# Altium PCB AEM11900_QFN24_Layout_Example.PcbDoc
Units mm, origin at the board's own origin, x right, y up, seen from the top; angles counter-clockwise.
Board outline 76 x 49 mm, 4 copper layers (Component Side, Ground Plane, Power Plane, Solder Side), stack 1.563 mm thick; 9 components, 21 nets, 41 pads, 18 vias.
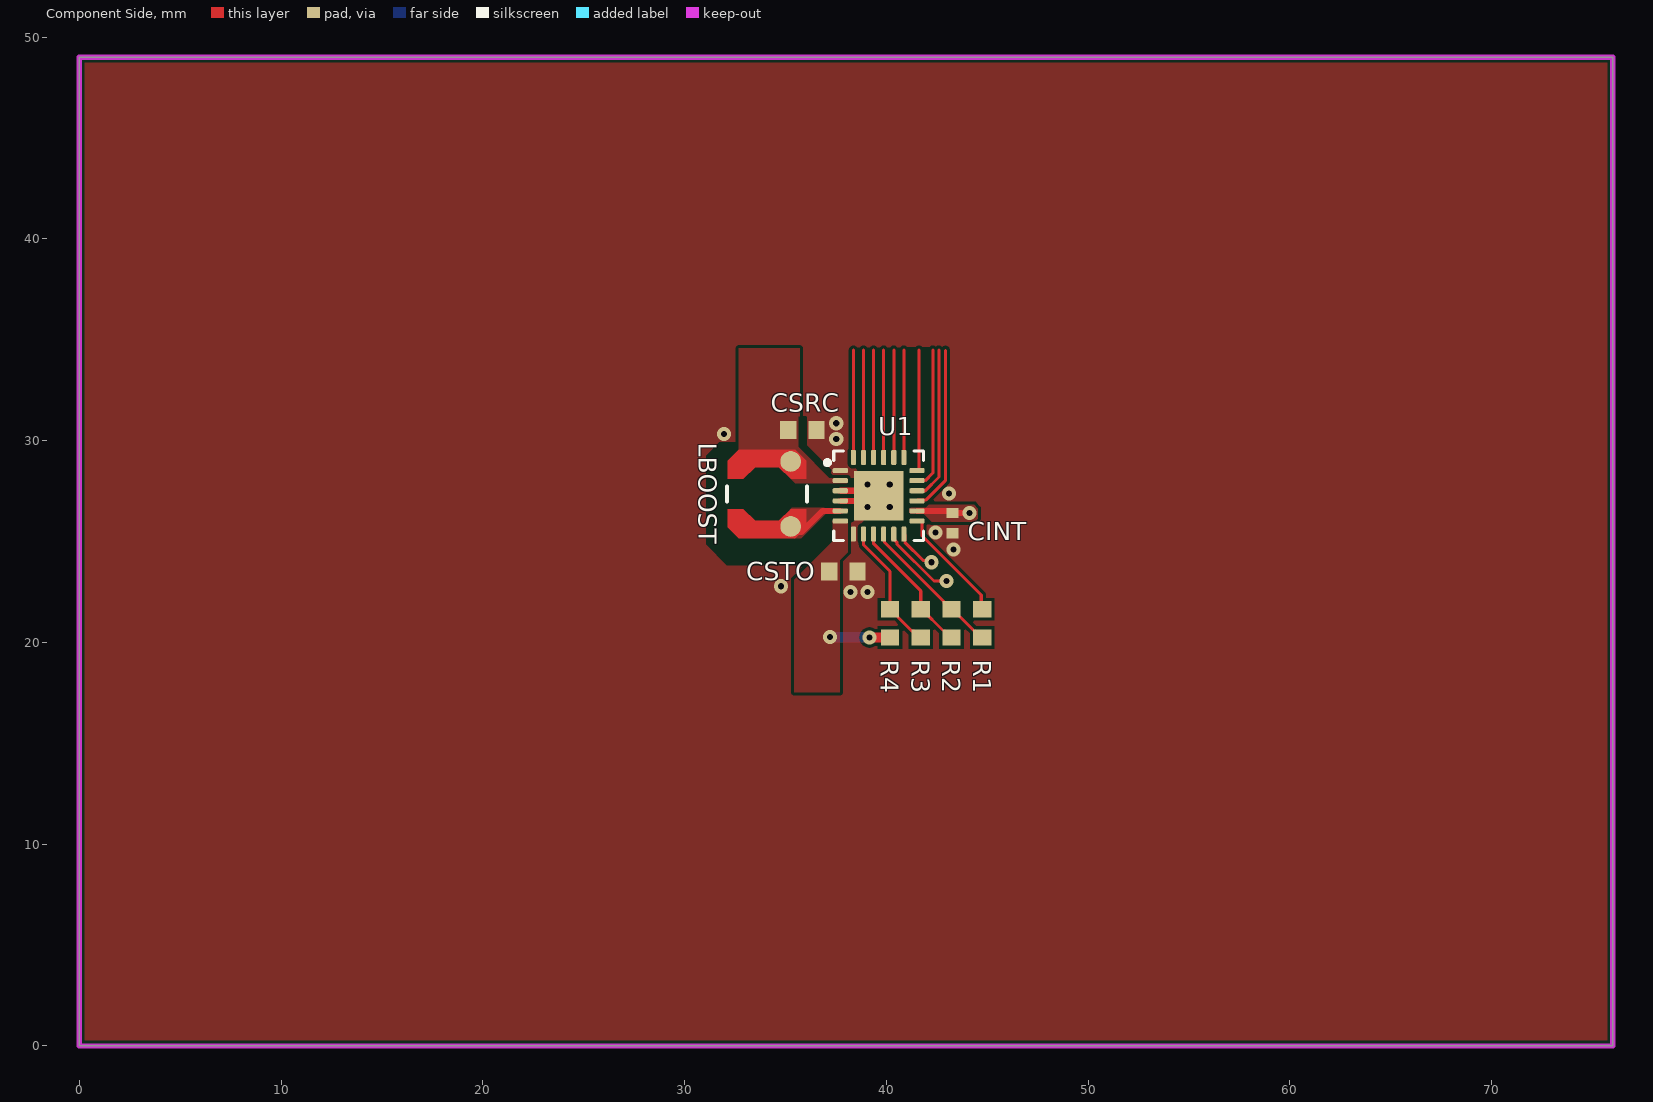
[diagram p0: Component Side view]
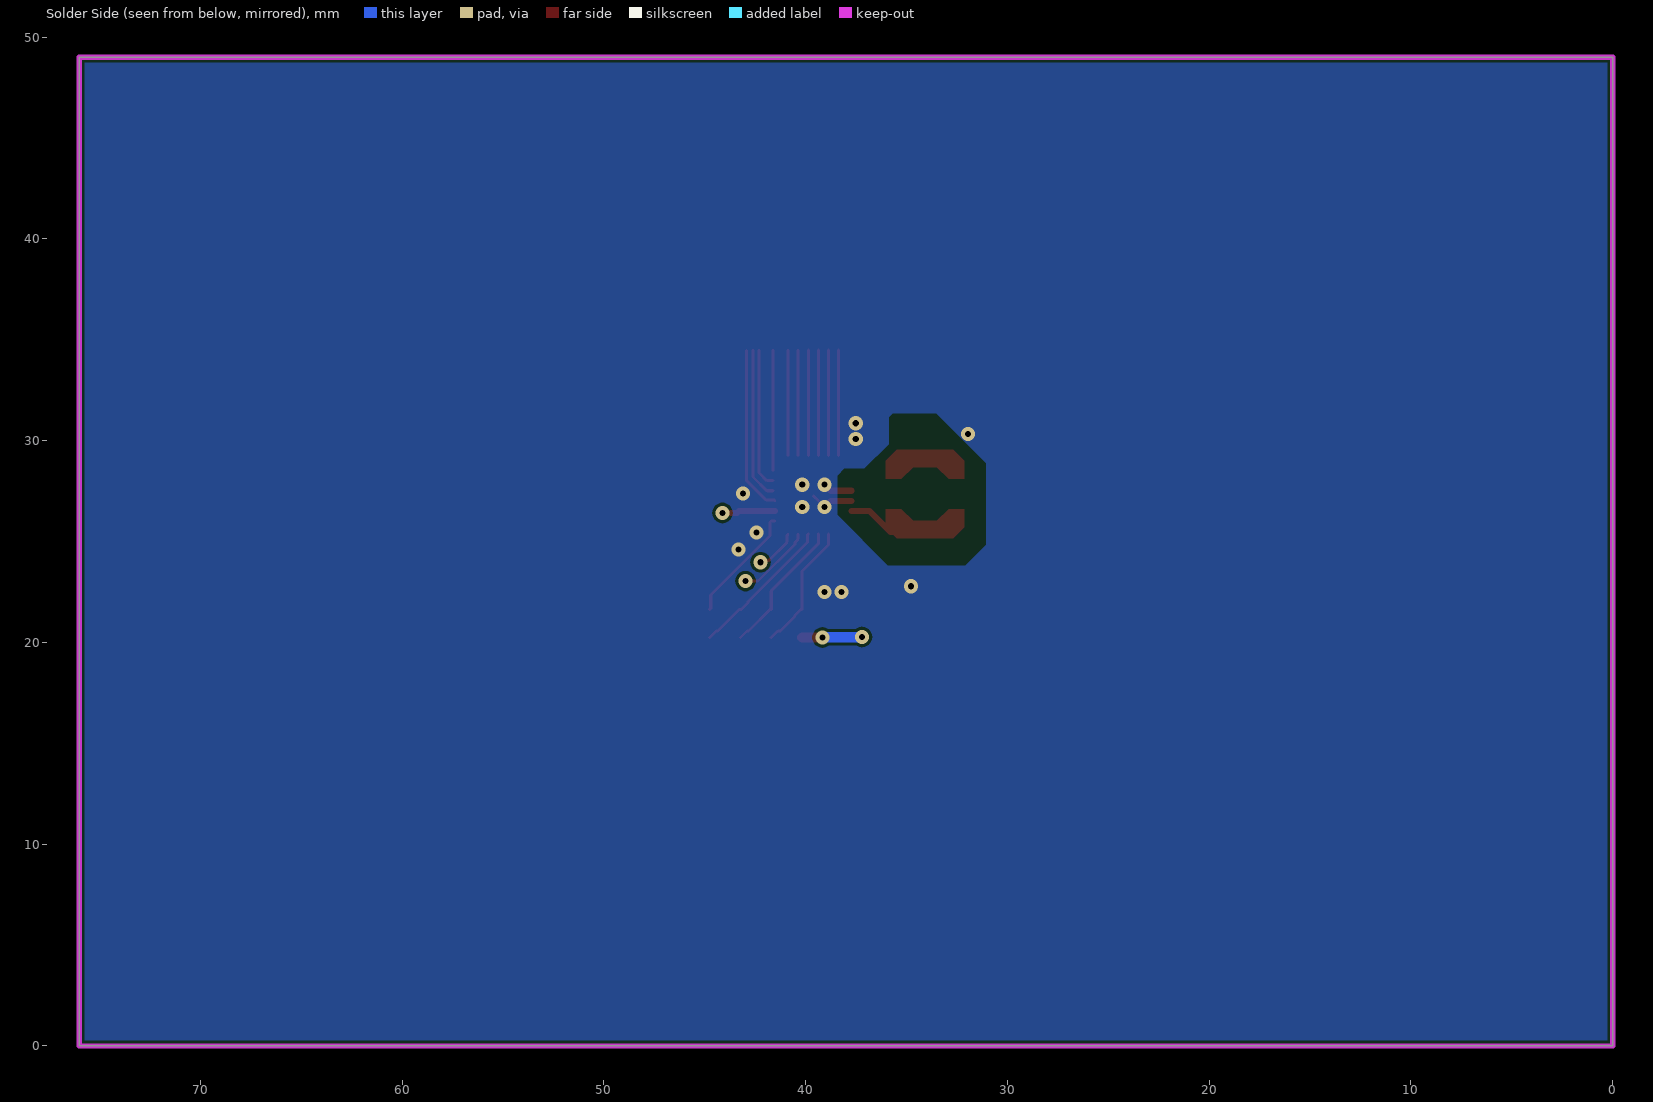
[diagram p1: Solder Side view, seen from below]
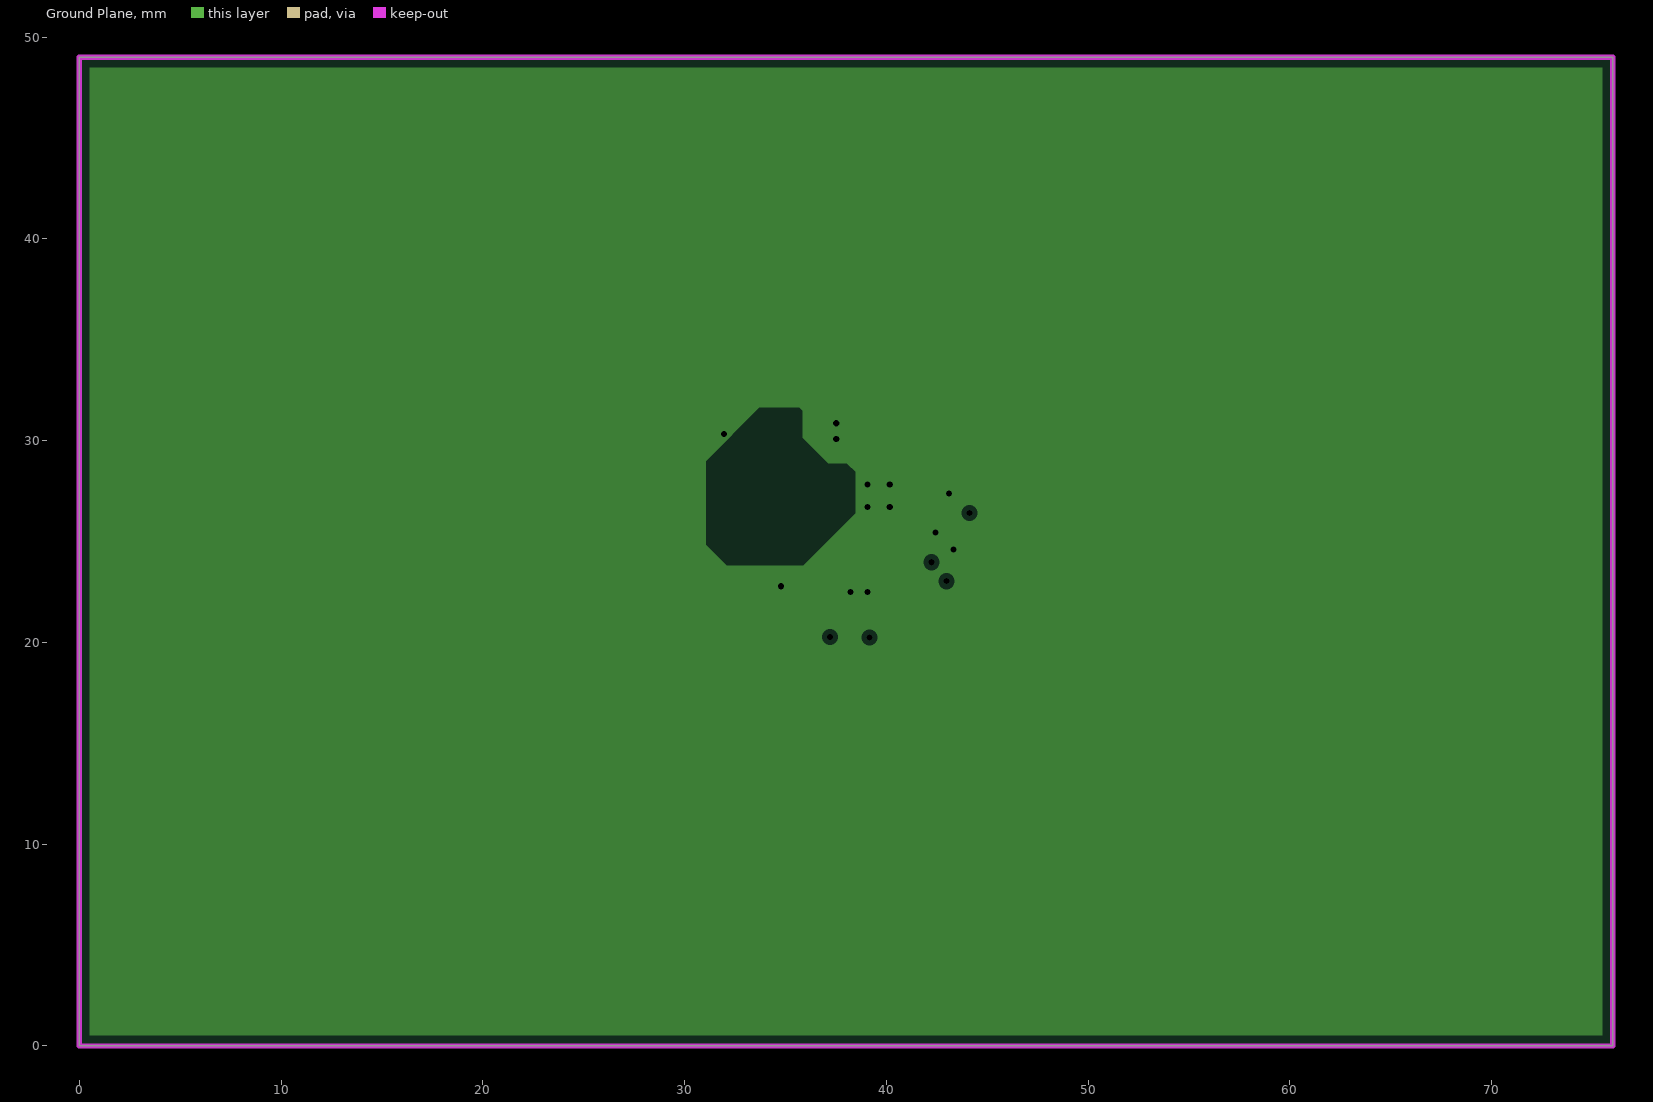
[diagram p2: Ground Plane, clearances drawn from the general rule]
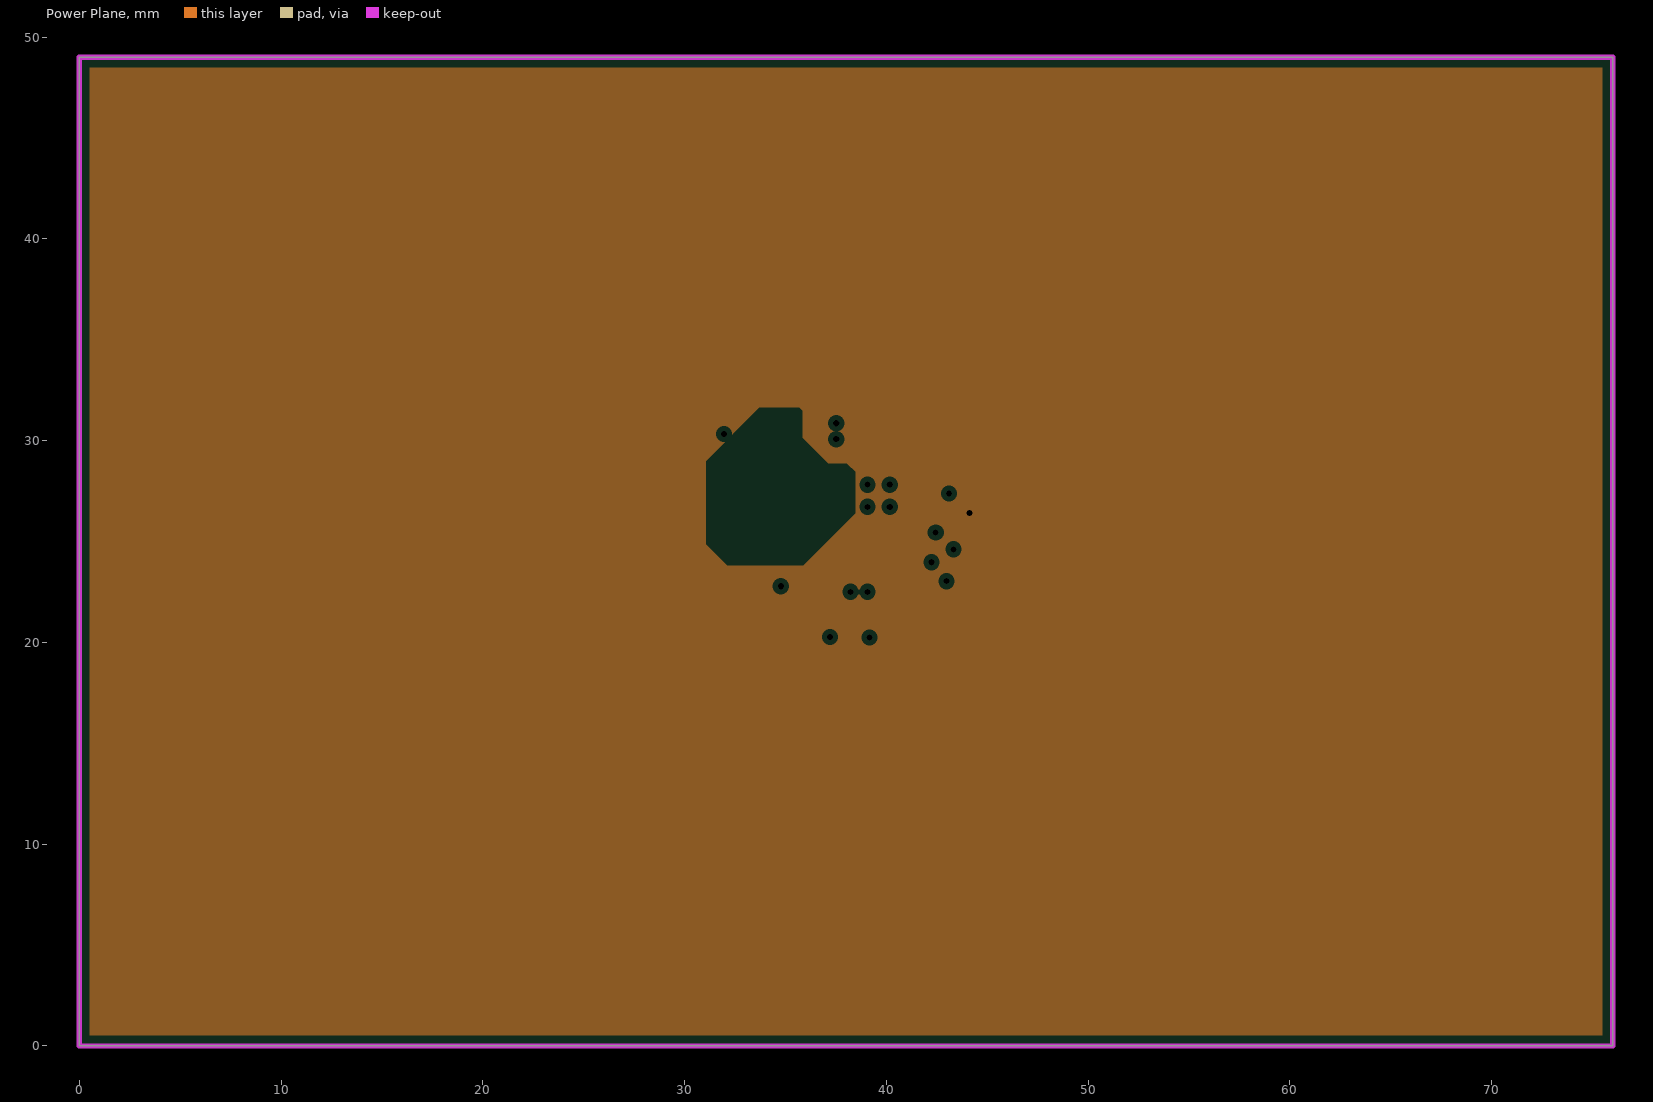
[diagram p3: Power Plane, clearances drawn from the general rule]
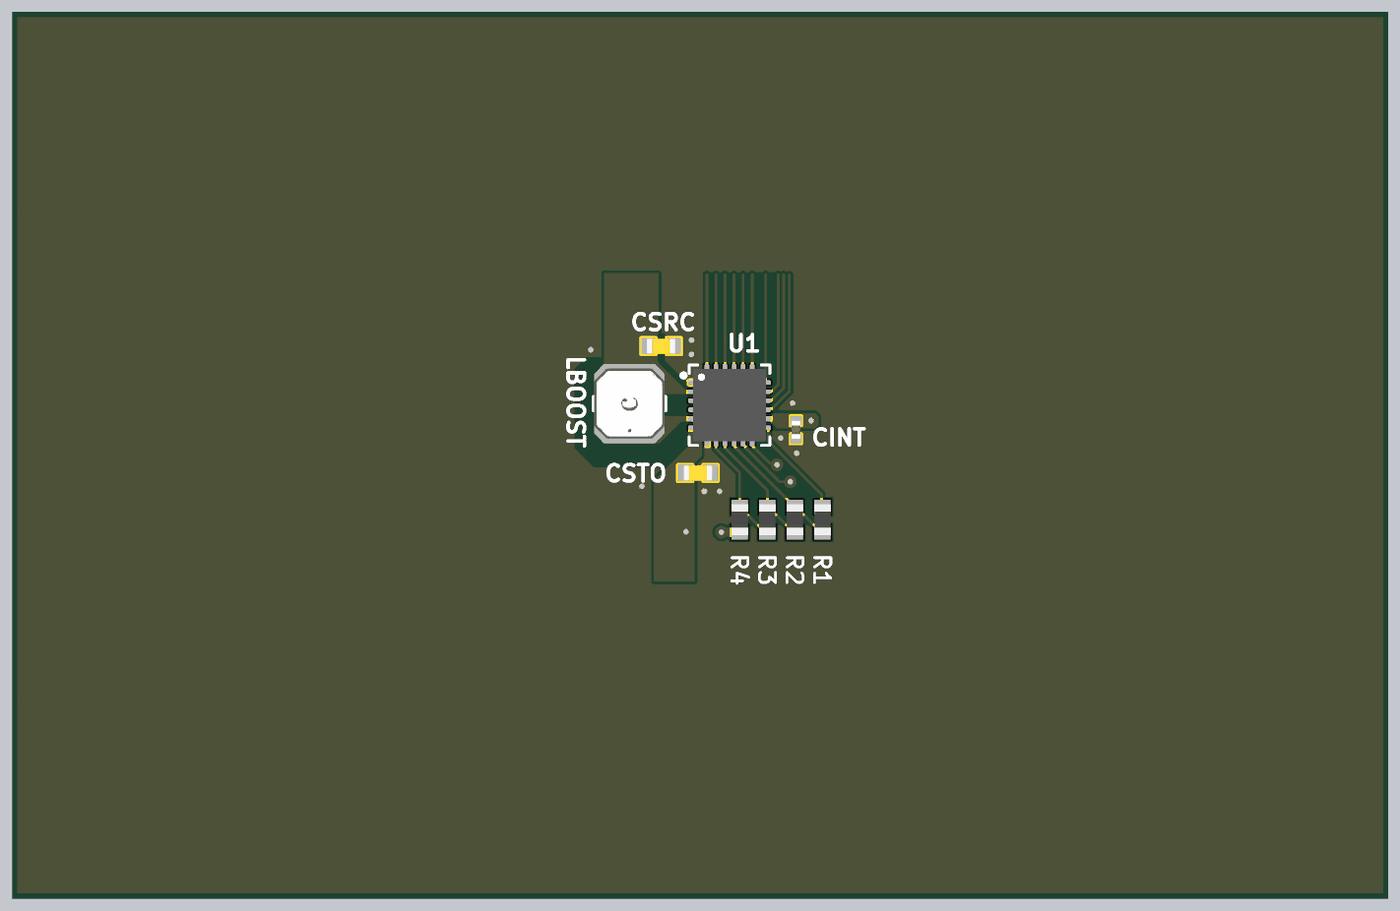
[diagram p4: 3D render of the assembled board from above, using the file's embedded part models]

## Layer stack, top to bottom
Top Solder: solder mask 0.0102, Solder Resist, Dk 3.5
Component Side: signal copper 0.0356
Dielectric 1: prepreg 0.36, Prepreg 7628, Dk 4.2
Ground Plane: plane copper 0.036, net GND
Dielectric 3: core 0.7, Core, Dk 4.2
Power Plane: plane copper 0.036, net VINT
Dielectric 4: prepreg 0.36, Prepreg 7628, Dk 4.2
Solder Side: signal copper 0.0356
Bottom Solder: solder mask 0.0102, Solder Resist, Dk 3.5

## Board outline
0,0 0,49 76,49 76,0

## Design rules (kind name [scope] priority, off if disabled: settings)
Clearance Clearance_SW [InNet('SWBOOST') or InNet('SWBUCK') vs InNet('GND')] p1: gap=0.15 ignorepadtopadclearanceinfootprint=FALSE except(0.5: Arc-Poly Track-Poly SMDPad-Poly THPad-Poly Via-Poly Fill-Poly Poly-Poly Poly-Region)
Clearance [All] p2: gap=0.15 ignorepadtopadclearanceinfootprint=FALSE
ComponentClearance ComponentClearance_DIL [HasFootprint('DIL_PAD') vs HasFootprint('DIL_PAD')] p1: gap=0 collisioncheckmode=3 verticalgap=0 showdistances=FALSE
ComponentClearance [All] p2: gap=0.254 collisioncheckmode=3 verticalgap=0.254 showdistances=FALSE
DiffPairsRouting [All] p1: maxlimit=0.254 minlimit=0.254 mostfreqgap=0.254 toplayer_minwidth=0.381 toplayer_maxwidth=0.381 toplayer_prefwidth=0.381 bottomlayer_minwidth=0.381 bottomlayer_maxwidth=0.381 bottomlayer_prefwidth=0.381 substack1={24748C9E-C2FE-4590-BE0C-AD6E21E98903} toplayer_{24748c9e-c2fe-4590-be0c-ad6e21e98903}_minwidth=0.381 toplayer_{24748c9e-c2fe-4590-be0c-ad6e21e98903}_maxwidth=0.381 toplayer_{24748c9e-c2fe-4590-be0c-ad6e21e98903}_prefwidth=0.381 bottomlayer_{24748c9e-c2fe-4590-be0c-ad6e21e98903}_minwidth=0.381 bottomlayer_{24748c9e-c2fe-4590-be0c-ad6e21e98903}_maxwidth=0.381 bottomlayer_{24748c9e-c2fe-4590-be0c-ad6e21e98903}_prefwidth=0.381 substack2={CAEF0C9C-1F67-4FFA-A1CA-0FD6FF6C2F90} toplayer_{caef0c9c-1f67-4ffa-a1ca-0fd6ff6c2f90}_minwidth=0.381 toplayer_{caef0c9c-1f67-4ffa-a1ca-0fd6ff6c2f90}_maxwidth=0.381 toplayer_{caef0c9c-1f67-4ffa-a1ca-0fd6ff6c2f90}_prefwidth=0.381 bottomlayer_{caef0c9c-1f67-4ffa-a1ca-0fd6ff6c2f90}_minwidth=0.381 bottomlayer_{caef0c9c-1f67-4ffa-a1ca-0fd6ff6c2f90}_maxwidth=0.381 bottomlayer_{caef0c9c-1f67-4ffa-a1ca-0fd6ff6c2f90}_prefwidth=0.381 substack3={D99B185B-21CD-406C-9F05-D1849F64E374} toplayer_{d99b185b-21cd-406c-9f05-d1849f64e374}_minwidth=0.381 toplayer_{d99b185b-21cd-406c-9f05-d1849f64e374}_maxwidth=0.381 toplayer_{d99b185b-21cd-406c-9f05-d1849f64e374}_prefwidth=0.381 bottomlayer_{d99b185b-21cd-406c-9f05-d1849f64e374}_minwidth=0.381 bottomlayer_{d99b185b-21cd-406c-9f05-d1849f64e374}_maxwidth=0.381 bottomlayer_{d99b185b-21cd-406c-9f05-d1849f64e374}_prefwidth=0.381 maxuncoupledlength=12.7
HoleToHoleClearance [All] p1: gap=0.2 allowstackedmicrovias=TRUE
MinimumAnnularRing [All] p1: minimumring=0.15
MinimumSolderMaskSliver [All] p1: minsoldermaskwidth=0
PlaneClearance [All] p1: clearance=0.254
PlaneConnect "Plane Force direct connect" [InComponent('M1') or InComponent('M2') or InComponent('M3') or InComponent('M4') or InComponent('TP1') or InComponent('TP2') or InComponent('TP3')] p1: planeconnectstyle=Direct reliefexpansion=0.508 reliefentries=4 reliefconductorwidth=0.5 reliefairgap=0.254
PlaneConnect [All] p2: pad.planeconnectstyle=Relief pad.reliefexpansion=0.2 pad.reliefentries=4 pad.reliefconductorwidth=0.5 pad.reliefairgap=0.15 via.planeconnectstyle=Direct via.reliefexpansion=0.2 via.reliefentries=4 via.reliefconductorwidth=0.254 via.reliefairgap=0.15
PolygonConnect "Poly Force direct connect" [InComponent('M1') or InComponent('M2') or InComponent('M3') or InComponent('M4')] p1: connectstyle=Direct reliefconductorwidth=0.254 reliefentries=4 polygonreliefangle="90 Angle" airgapwidth=0.254
PolygonConnect [All] p2: thpad.connectstyle=Relief thpad.reliefconductorwidth=0.35 thpad.reliefentries=4 thpad.polygonreliefangle="90 Angle" thpad.airgapwidth=0.15 smdpad.connectstyle=Direct smdpad.reliefconductorwidth=0.5 smdpad.reliefentries=4 smdpad.polygonreliefangle="90 Angle" smdpad.airgapwidth=0.15 via.connectstyle=Direct via.reliefconductorwidth=0.35 via.reliefentries=4 via.polygonreliefangle="90 Angle" via.airgapwidth=0.15
RoutingVias [All] p1: holewidth=0.3 width=0.7 viastyle="Through Hole" minholewidth=0.3 minwidth=0.7 maxholewidth=0.3 maxwidth=0.7
SilkToSilkClearance [All] p1: silktosilkclearance=0
SilkToSolderMaskClearance [IsPad] p1: minsilkscreentomaskgap=0.1 clearancetoexposedcopper=TRUE
SolderMaskExpansion "tented vias" [IsVia] p1: expansion=0.15 istentingtop=TRUE
SolderMaskExpansion [All] p2: expansion=0.11 istentingtop=FALSE
SupplyNets "Schematic Supply Nets_2" [InNet('STO')] p1: voltage=0.000
SupplyNets "Schematic Supply Nets_1" [InNet('GND')] p2: voltage=0.000
SupplyNets "Schematic Supply Nets" [InNet('VINT')] p3: voltage=0.000
Width [All] p1: maxlimit=2 minlimit=0.15 preferedwidth=0.2 substack1={24748C9E-C2FE-4590-BE0C-AD6E21E98903} substack2={CAEF0C9C-1F67-4FFA-A1CA-0FD6FF6C2F90} substack3={D99B185B-21CD-406C-9F05-D1849F64E374} minimp=50.000000 maximp=50.000000 favimp=50.000000
22 further rules are at their usual default settings.

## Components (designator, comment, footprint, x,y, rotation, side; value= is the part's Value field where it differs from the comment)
CINT "10uF" C0402_[1005] 43.282,25.908 r90 top
CSRC "10uF" C0603_[1608] 35.839,30.531 r180 top
CSTO "47uF" C0603_[1608] 37.871,23.52 r180 top
LBOOST "33uH" Coilcraft-LPS4018 34.087,27.356 r90 top
R1 "TBD" Resistor_0603_[1608] 44.753,20.941 r270 top
R2 "TBD" Resistor_0603_[1608] 43.229,20.941 r270 top
R3 "TBD" Resistor_0603_[1608] 41.705,20.941 r270 top
R4 "TBD" Resistor_0603_[1608] 40.181,20.941 r270 top
U1 "AEM11900_QFN24" QFN24_4x4mm_PITCH_0.5mm_PAD_2.45mm 39.617,27.266 r0 top

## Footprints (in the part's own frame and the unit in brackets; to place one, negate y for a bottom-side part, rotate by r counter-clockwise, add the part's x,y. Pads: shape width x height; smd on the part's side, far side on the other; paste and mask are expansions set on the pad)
C0402_[1005] [mm] "Chip Capacitor, Body 1.0x0.5mm, IPC High Density"
  rect 0.5x0.6 smd: 1(-0.5,0) 2(0.5,0)
  body extent -0.5,-0.25 0.5,0.25, height 0.7
C0603_[1608] [mm]
  rect 0.8x0.9 smd: 1(-0.7,0) 2(0.7,0)
  body extent -0.8,-0.43 0.8,0.43, height 0.8
Coilcraft-LPS4018 [mm]
  round 1.026 smd paste+0 mask+0: 1(-1.611,-1.175) 2(1.611,-1.175)
  Component Side region: 0.75,1.945 1.64,1.945 2.2,1.395 2.2,-1.395 1.64,-1.945 0.75,-1.945 0.75,-1.17 1.33,-0.575 1.33,0.575 0.75,1.17
  Component Side region: -0.75,1.945 -1.64,1.945 -2.2,1.395 -2.2,-1.395 -1.64,-1.945 -0.75,-1.945 -0.75,-1.17 -1.33,-0.575 -1.33,0.575 -0.75,1.17
  silkscreen extent -0.37,-1.99 0.37,1.99, body extent -2.3,-2.09 2.3,2.09, height 0.25
QFN24_4x4mm_PITCH_0.5mm_PAD_2.45mm [mm] "QFN, 24-Leads, Body 4.00x4.00mm, Pitch 0.50mm, Thermal Pad 2.45x2.45mm"
  rrect50% 0.75x0.25 smd: 1(-1.9,1.25) 2(-1.9,0.75) 3(-1.9,0.25) 4(-1.9,-0.25) 5(-1.9,-0.75) 6(-1.9,-1.25) 13(1.9,-1.25) 14(1.9,-0.75) 15(1.9,-0.25) 16(1.9,0.25) 17(1.9,0.75) 18(1.9,1.25)
  rrect50% 0.25x0.75 smd: 7(-1.25,-1.9) 8(-0.75,-1.9) 9(-0.25,-1.9) 10(0.25,-1.9) 11(0.75,-1.9) 12(1.25,-1.9) 19(1.25,1.9) 20(0.75,1.9) 21(0.25,1.9) 22(-0.25,1.9) 23(-0.75,1.9) 24(-1.25,1.9)
  rect 2.45x2.45 smd: 25(0,0)
  silkscreen extent -2.64,-2.23 2.23,2.22, body extent -2,-2 2,2, height 0.8
Resistor_0603_[1608] [mm]
  rect 0.8x0.9 smd: 1(-0.7,0) 2(0.7,0)
  body extent -0.85,-0.46 0.85,0.46, height 0.56

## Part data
CINT: library part "Cap Ceramic 10uF, 6.3V, 20%, X5R, 0402", "Cap Ceramic 10uF, 6.3V, 20%, X5R, 0402", Manuf=MURATA, Manuf PN=GRM155R60J106ME05D, Package=0402, Package Metric=1005
CSRC: library part "Cap Ceramic 10uF, 10V, 20%, X5R 0603", "Cap Ceramic 10uF, 10V, 20%, X5R 0603", Manuf=MURATA, Manuf PN=GRM188R61A106ME69D, Package=0603, Package Metric=1608
CSTO: library part "Cap Ceramic 47uF 6.3V +/-20% X5R 0603", "Cap Ceramic 47uF 6.3V +/-20% X5R 0603", Manuf=Murata, Manuf PN=GRM188R60J476ME15D, Package=0603, Package Metric=1608
LBOOST: library part "Power Inductor 33uH - 0.68A - LPS4018 - Small Symbol", "Power Inductor 33uH - 0,68A - LPS4018", Manuf=Coilcraft, Manuf PN=LPS4018-333MRB, Max DC Current=800mA, Package="4 x 4 x 1.8mm", Self Resonant Frequency=20MHz
R1 R2 R3 R4: library part "Resistor TBD - 0603", "Resistor TBD - 0603", Package=0603
U1: Manuf=e-peas, Manuf PN=10AEM11900A0001, Package=QFN24

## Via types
v1: diameter 0.7, hole 0.3, Component Side to Solder Side, tented both sides, 18 vias

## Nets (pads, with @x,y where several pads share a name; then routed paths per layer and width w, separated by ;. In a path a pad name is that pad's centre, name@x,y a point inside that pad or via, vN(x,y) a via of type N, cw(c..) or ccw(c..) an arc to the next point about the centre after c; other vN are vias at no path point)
BOOST_CFG: U1.17 | length 6.9
  Component Side w0.15: U1.17@41.617,28.016 41.923,28.016 42.304,28.398 42.304,34.479
CM_D: R1.1 U1.13 | length 5.8
  Component Side w0.15: U1.13 41.705,26.016 41.755,25.966 41.755,25.301 44.703,22.353 44.703,21.691 R1.1
GND: CINT.1 CSRC.1 CSTO.1 U1.1 U1.3 U1.4 U1.7 U1.25 | length 3.3
  Component Side w0.15: U1.25@38.767,27.516 v1(39.067,27.816) ; U1.25@39.367,27.016 U1.25
  Component Side w0.3: U1.4 38.767,27.016 v1(39.067,26.716) ; U1.3 U1.25@38.767,27.516
  other v1: 38.227,22.504 39.065,22.504 34.773,22.784 43.332,24.613 42.443,25.451 40.167,26.716 43.104,27.381 40.167,27.816 37.516,30.074 31.953,30.328 37.516,30.861
SET_CHRDY: R2.2 R3.1 U1.9 | length 6.8
  Component Side w0.15: U1.9 39.372,25.361 39.372,24.89 41.705,22.557 R3.1 41.755,21.641 42.83,20.566 42.904,20.566 R2.2
SET_OVCH: R1.2 R2.1 U1.10 | length 7.3
  Component Side w0.15: U1.10 39.917,25.316 39.917,24.953 42.854,22.016 42.854,21.966 43.179,21.641 R2.1 43.279,21.641 44.354,20.566 44.428,20.566 R1.2
SET_OVDIS: R3.2 R4.1 U1.8 | length 6.4
  Component Side w0.15: U1.8 38.867,24.836 40.181,23.522 R4.1 40.231,21.641 40.556,21.316 40.556,21.266 41.256,20.566 41.38,20.566 R3.2
SHIP_MODE: U1.12 | length 2.1
  Component Side w0.15: U1.12 40.917,25.316 40.917,24.97 41.819,24.069 42.14,24.069 v1(42.236,23.973)
SHIP_MODE_CFG: U1.15 | length 8.3
  Component Side w0.15: U1.15 41.567,27.066 41.976,27.066 42.924,28.015 42.924,34.468
SRC: CSRC.2 LBOOST.2 U1.2
SRC_CFG_0: U1.20 | length 5.2
  Component Side w0.15: U1.20@40.367,29.266 40.367,34.479
SRC_CFG_1: U1.21 | length 5.2
  Component Side w0.15: U1.21@39.867,29.266 39.867,34.479
SRC_CFG_2: U1.22 | length 5.2
  Component Side w0.15: U1.22@39.367,29.266 39.367,34.479
SRC_CFG_3: U1.23 | length 5.2
  Component Side w0.15: U1.23@38.867,29.266 38.867,34.479
SRC_CFG_4: U1.24 | length 5.2
  Component Side w0.15: U1.24@38.367,29.266 38.367,34.479
SRC_MODE: U1.16 | length 7.6
  Component Side w0.15: U1.16@41.617,27.516 41.923,27.516 42.604,28.198 42.604,34.479
ST_STO: U1.11 | length 3.8
  Component Side w0.15: U1.11 40.367,25.116 40.517,24.966 40.517,24.879 42.359,23.038 v1(42.977,23.038)
STO: CSTO.2 R4.2 U1.6 | length 3
  Component Side w0.5: v1(39.167,20.244) 39.168,20.242 40.18,20.242 R4.2
  Solder Side w0.5: v1(37.211,20.269) 37.224,20.256 39.154,20.256 v1(39.167,20.244)
STO_CFG_0: U1.18 | length 6
  Component Side w0.15: U1.18@41.617,28.516 41.617,34.479
STO_CFG_1: U1.19 | length 5.2
  Component Side w0.15: U1.19@40.867,29.266 40.867,34.479
SWBOOST: LBOOST.1 U1.5 | length 2.9
  Component Side w0.3: LBOOST.1@35.261,25.465 35.788,25.465 36.839,26.516 U1.5
VINT: CINT.2 U1.14 | length 2.6
  Component Side w0.3: U1.14 42.962,26.516 42.97,26.508 43.309,26.508 43.405,26.412 44.116,26.412 v1(44.12,26.416)

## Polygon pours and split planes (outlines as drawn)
GND on Component Side "TOP GND" (solid, remove dead copper, pour order 66): 76,49 0,49 0,0 76,0
VINT on Component Side "POLY_VINT_TOP" (solid, remove dead copper, pour order 61): 41.142,26.422 41.142,26.613 41.199,26.67 41.941,26.67 42.103,26.832 44.351,26.832 44.526,26.635 44.526,26.137 44.374,25.984 42.24,25.984 41.859,26.365 41.199,26.365
SRC on Component Side "POLY_SRC_TOP" (solid, remove dead copper, pour order 64): 38.075,27.925 38.075,28.118 38.049,28.143 37.16,28.143 35.706,29.613 35.706,34.569 32.69,34.569 32.69,29.553 33.82,29.553 35.484,27.889 38.049,27.889
SWBOOST on Component Side "POLY_SWBOOST_TOP" (solid, remove dead copper, pour order 59): 38.092,26.408 38.051,26.367 36.984,26.367 35.775,25.158 35.472,25.158 35.212,26.562 35.32,26.67 38.049,26.67 38.092,26.627
STO on Component Side "POLY_STO_TOP" (solid, remove dead copper, pour order 62): 38.089,26.01 38.089,24.475 37.694,24.079 37.694,17.526 35.433,17.526 35.433,23.114 37.344,25.025 37.344,26.01
GND on Solder Side "TOP GND" (solid, remove dead copper, pour order 56): 76,49 0,49 0,0 76,0
VINT on Power Plane (split plane): 75.49,0.51 0.51,0.51 0.51,48.49 75.49,48.49
GND on Ground Plane (split plane): 75.49,0.51 0.51,0.51 0.51,48.49 75.49,48.49

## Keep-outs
Keep-Out Layer:
  the board outline again, w0.25

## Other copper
Component Side:
  pour cut-out: 37.236,28.143 35.636,29.693 35.636,31.217 36.017,31.217 36.043,31.191 36.043,29.769 37.262,28.55
  pour cut-out: 36.043,27.788 36.043,26.772 36.373,26.772 37.211,26.772 37.211,27.788
  pour cut-out: 40.995,25.857 38.74,25.857 39.091,26.264 38.133,26.284 38.133,26.693 38.545,26.697 38.562,27.787 38.232,27.784 38.221,28.129 38.837,28.129 38.481,28.651 40.995,28.651
  pour cut-out: 42.215,34.62 41.707,34.62 41.834,34.493 42.088,34.493
  pour cut-out: 41.465,34.62 40.957,34.62 41.084,34.493 41.338,34.493
  pour cut-out: 35.89,23.825 37.262,25.197 37.262,26.213 36.982,26.213 35.535,24.765 32.614,24.765 32.04,25.336 32.038,29.016 32.562,29.541 32.562,29.921 31.725,29.921 31.064,29.261 31.064,24.873 32.099,23.825
Solder Side:
  pour cut-out: 35.926,23.825 32.08,23.825 31.064,24.841 31.064,28.88 33.528,31.344 35.687,31.344 35.865,31.166 35.865,29.82 37.084,28.6 38.075,28.6 38.405,28.27 38.405,26.331
Ground Plane (plane layer: these items are gaps in the copper):
  pour cut-out: 38.049,28.854 37.113,28.854 35.834,30.133 35.834,31.47 35.687,31.617 33.7,31.617 31.064,28.981 31.064,24.841 32.08,23.825 35.89,23.825 38.456,26.391 38.456,28.448
Power Plane (plane layer: these items are gaps in the copper):
  pour cut-out: 38.049,28.854 37.113,28.854 35.834,30.133 35.834,31.47 35.687,31.617 33.7,31.617 31.064,28.981 31.064,24.867 32.106,23.825 35.89,23.825 38.456,26.391 38.456,28.448
  lines w0.254: 38.227,22.504 39.065,22.504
